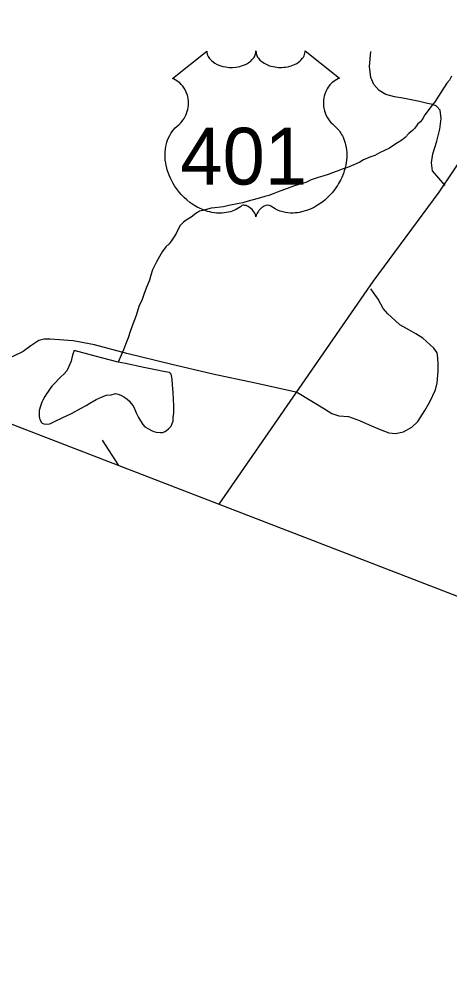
# Model space of a CAD drawing. Extents: x 2001466 to 2224147, y 644118 to 847247.
# Drawn here: x 2055061 to 2056671, y 653811 to 657420 of the extents above; entities that cross this region are included whole.
import ezdxf

# ---------------------------------------------------------------- set-up
doc = ezdxf.new("R2010")
doc.units = 0
for name, color, linetype in [('Exist Boundary Political CountyLine', 7, 'Continuous'), ('Exist Hydrographic Misc Water Feature', 7, 'Continuous'), ('Exist Road Non-System Type 51', 7, 'Continuous'), ('Exist Road Primary US Attributed', 7, 'Continuous'), ('Exist Road Primary US Shield CELL', 7, 'Continuous'), ('Exist Road Primary US Shield Number Label', 7, 'Continuous')]:
    doc.layers.add(name, color=color, linetype=linetype)

msp = doc.modelspace()

# ---------------------------------------------------------------- linework, layer by layer
at = {"layer": 'Exist Boundary Political CountyLine'}
msp.add_lwpolyline([(2025347, 667357.1), (2026293.9, 666990.5), (2073692.9, 648709.4), (2076162.7, 647794.5), (2078580.1, 646988.2), (2083338.8, 645254.9), (2086621.1, 644117.9)], dxfattribs=at)
at = {"layer": 'Exist Hydrographic Misc Water Feature'}
for points in [[(2056677.9, 657206.8), (2056669.9, 657192.8), (2056660.1, 657180.8), (2056652.1, 657166.8), (2056642, 657152.7), (2056632.2, 657136.7), (2056624.2, 657124.7), (2056616.2, 657112.7), (2056600.2, 657092.7), (2056590.2, 657078.7), (2056578.3, 657062.6), (2056570.3, 657048.6), (2056562.3, 657036.6), (2056552.2, 657028.6), (2056540.3, 657012.6), (2056532.3, 657004.6), (2056518.4, 656992.6), (2056504.5, 656978.5), (2056492.4, 656968.5), (2056476.4, 656958.5), (2056458.5, 656946.4), (2056446.4, 656938.4), (2056424.5, 656928.3), (2056408.5, 656920.3), (2056390.4, 656910.3), (2056372.4, 656904.3), (2056348.6, 656894.2), (2056334.7, 656886.2), (2056312.5, 656876.1), (2056288.5, 656866.1), (2056268.6, 656860.1), (2056250.6, 656852.1), (2056232.6, 656846.1), (2056216.8, 656840), (2056196.7, 656834), (2056178.8, 656827.9), (2056152.8, 656819.9), (2056132.7, 656809.9), (2056106.7, 656801.8), (2056086.8, 656795.8), (2056060.9, 656785.7), (2056034.9, 656777.7), (2056010.9, 656767.6), (2055994.9, 656761.6), (2055978.9, 656757.5), (2055954.9, 656749.5), (2055930.9, 656743.5), (2055917, 656739.5), (2055897.1, 656733.4), (2055882.9, 656731.4), (2055863.1, 656727.3), (2055845, 656723.3), (2055824.9, 656719.3), (2055813, 656717.3), (2055792.9, 656715.2), (2055779, 656713.2), (2055747, 656705.1), (2055734.9, 656703.1), (2055726.9, 656697.1), (2055717.1, 656691.1), (2055707.2, 656683.1), (2055697.2, 656677), (2055685.1, 656669), (2055675, 656661), (2055663.1, 656648.9), (2055655.3, 656635), (2055647.3, 656619), (2055639.1, 656605), (2055629.3, 656591), (2055621.3, 656580.9), (2055609.4, 656568.9), (2055595.5, 656550.9), (2055585.4, 656532.8), (2055573.3, 656510.8), (2055559.6, 656482.9), (2055553.4, 656462.8), (2055547.7, 656444.8), (2055537.6, 656420.8), (2055527.6, 656394.8), (2055519.8, 656372.8), (2055507.7, 656346.8), (2055497.9, 656312.8), (2055485.8, 656280.7), (2055475.9, 656252.7), (2055467.9, 656228.7), (2055458.1, 656204.7), (2055450.1, 656184.7), (2055442.1, 656164.7), (2055430.2, 656138.6)], [(2055430.2, 656138.6), (2055368.1, 656154.5), (2055266.1, 656182.3), (2055260.2, 656164.3), (2055256.1, 656148.3), (2055254.1, 656142.3), (2055246.3, 656122.3), (2055238.3, 656106.3), (2055228.2, 656094.3), (2055214.3, 656082.3), (2055190.3, 656056.2), (2055182.3, 656048.2), (2055176.3, 656040.2), (2055168.3, 656028.2), (2055162.4, 656020.2), (2055156.4, 656010.2), (2055148.4, 655996.1), (2055144.6, 655988.1), (2055140.5, 655974.1), (2055134.5, 655958.1), (2055134.5, 655946.1), (2055134.5, 655936.1), (2055136.6, 655928.1), (2055138.6, 655922.1), (2055142.5, 655914.1), (2055146.6, 655910.1), (2055152.5, 655908.2), (2055162.6, 655906.2), (2055174.7, 655908.2), (2055184.5, 655912.2), (2055194.6, 655918.2), (2055220.6, 655930.2), (2055256.5, 655946.4), (2055292.4, 655966.4), (2055310.4, 655976.4), (2055324.4, 655984.5), (2055348.4, 655998.5), (2055370.3, 656008.6), (2055386.3, 656014.6), (2055404.4, 656016.6), (2055420.3, 656020.7), (2055430.4, 656018.6), (2055440.4, 656014.7), (2055452.3, 656008.7), (2055462.4, 656000.7), (2055472.4, 655992.8), (2055478.4, 655984.8), (2055486.4, 655974.8), (2055492.5, 655960.8), (2055498.5, 655948.9), (2055506.5, 655930.9), (2055514.5, 655918.8), (2055522.7, 655904.9), (2055530.7, 655896.9), (2055544.6, 655888.9), (2055554.7, 655883), (2055564.5, 655879), (2055572.5, 655877), (2055588.7, 655875), (2055596.7, 655875), (2055606.5, 655879), (2055618.6, 655889), (2055628.5, 655899.1), (2055632.4, 655909.1), (2055636.5, 655917.1), (2055636.5, 655931.1), (2055638.5, 655947.1), (2055638.3, 655967.1), (2055638.3, 655975.1), (2055636.3, 656025.1), (2055634.2, 656053), (2055632.2, 656075), (2055628.3, 656093), (2055622.3, 656099), (2055600.2, 656102.9), (2055576.2, 656108.9), (2055526.2, 656118.8), (2055458.1, 656132.7), (2055430.2, 656138.6)]]:
    msp.add_lwpolyline(points, dxfattribs=at)
at = {"layer": 'Exist Road Non-System Type 51'}
msp.add_line((2055433.5, 655751.8), (2055372.2, 655846.2), dxfattribs=at)
for points in [[(2056653.6, 656798.2), (2056606.7, 656853.1), (2056603.3, 656883.2), (2056608, 656917.1), (2056623, 656964.8), (2056633.8, 657008.6), (2056638.7, 657048.5), (2056635.3, 657080.5), (2056621.6, 657094.8), (2056607.7, 657101.1), (2056587.8, 657105.5), (2056558, 657112.1), (2056496.2, 657125.4), (2056464.3, 657130), (2056432.5, 657138.7), (2056406.8, 657153.2), (2056387.2, 657175.6), (2056375.8, 657201.8), (2056370.6, 657243.9), (2056375.8, 657299.8)], [(2056101.8, 656025.4), (2056202.6, 655963.3), (2056230.2, 655946.8), (2056256.1, 655938.2), (2056292, 655935.5), (2056333.7, 655920.7), (2056369.4, 655903.9), (2056411, 655887.1), (2056442.8, 655874.4), (2056468.7, 655871.9), (2056498.8, 655877.3), (2056529.2, 655894.7), (2056551.6, 655916.2), (2056578.5, 655957.7), (2056597.1, 655989.3), (2056618, 656034.9), (2056624.6, 656060.8), (2056627.4, 656104.7), (2056628, 656130.7), (2056626.5, 656154.7), (2056624.8, 656172.8), (2056611.2, 656191), (2056570, 656227.9), (2056544.3, 656244.4), (2056518.6, 656258.9), (2056485, 656277.6), (2056467.3, 656293.9), (2056439.8, 656318.5), (2056422.2, 656338.9), (2056402.9, 656373.3), (2056375.7, 656411.8)], [(2056101.8, 656025.4), (2055938.6, 656060.7), (2055785.2, 656093.8), (2055626, 656131), (2055462.8, 656170.3), (2055341.4, 656202.8), (2055261.8, 656218.4), (2055175.9, 656224.2), (2055153.9, 656224.6), (2055133.8, 656219), (2055103.4, 656199.6), (2055074.9, 656178.2), (2055036.6, 656159), (2055000.3, 656147.7), (2054950.3, 656148.8), (2054916.5, 656155.4), (2054880.9, 656176.2), (2054831.8, 656221.2), (2054814, 656229.5), (2054734.3, 656247.1), (2054680.6, 656260.2), (2054619.1, 656283.5), (2054555.2, 656290.8)]]:
    msp.add_lwpolyline(points, dxfattribs=at)
at = {"layer": 'Exist Road Primary US Attributed'}
msp.add_lwpolyline([(2055808.3, 655607.2), (2056384.5, 656440.3), (2056631.5, 656773.3), (2056739.3, 656932.5), (2056804.2, 657056.1), (2056839.7, 657137.8), (2057035.4, 657847.8), (2057102.4, 658134.8), (2057229.1, 658557.8), (2057280.9, 658755.8), (2057376.1, 659063.7), (2057472.4, 659331.8), (2057516.3, 659409.3), (2057768.5, 659813.5), (2058800.4, 661326.8)], dxfattribs=at)
at = {"layer": 'Exist Road Primary US Shield CELL'}
msp.add_lwpolyline([(2055762, 657301.2), (2055762.4, 657295.9), (2055763.6, 657289.6), (2055764.6, 657286.3), (2055767.6, 657280.1), (2055772.5, 657272.7), (2055779.3, 657265.5), (2055786.9, 657259.2), (2055792.1, 657255.8), (2055800.9, 657251.1), (2055810.8, 657246.9), (2055821.9, 657243.7), (2055833.2, 657241.5), (2055845.6, 657240.1), (2055857.8, 657239.9), (2055871, 657240.9), (2055885.6, 657243.7), (2055892.4, 657245.4), (2055899.9, 657248), (2055906.9, 657250.9), (2055914.6, 657255), (2055920.7, 657258.9), (2055925.5, 657262.4), (2055932.4, 657269), (2055937.8, 657275.7), (2055940.1, 657279.5), (2055942, 657283.2), (2055944.7, 657290.9), (2055945.5, 657294.4), (2055946, 657301.5), (2055946.5, 657295.5), (2055947.1, 657291.8), (2055948.1, 657288.1), (2055949.6, 657284.2), (2055952.3, 657278.8), (2055955.4, 657274.2), (2055961.1, 657267.5), (2055964.7, 657264.1), (2055967.9, 657261.5), (2055976.7, 657255.4), (2055986.9, 657250.3), (2055991.9, 657248.1), (2055997.1, 657246.3), (2056003.6, 657244.3), (2056010.4, 657242.7), (2056017, 657241.5), (2056023.9, 657240.6), (2056030.9, 657240), (2056036.6, 657239.9), (2056043.6, 657239.9), (2056050, 657240.3), (2056056.6, 657241.1), (2056063.9, 657242.3), (2056069.8, 657243.6), (2056077.5, 657245.6), (2056084.5, 657248.2), (2056090.6, 657250.8), (2056098.6, 657255), (2056105.1, 657259), (2056109.8, 657262.8), (2056115.4, 657268), (2056120.7, 657274.1), (2056123.8, 657278.6), (2056126, 657283.3), (2056128.1, 657288.1), (2056129.3, 657293.3), (2056129.9, 657297.8), (2056130.1, 657301.6), (2056258.7, 657199.2), (2056255.6, 657198), (2056248.6, 657194.6), (2056243.1, 657191.3), (2056234.3, 657185.1), (2056230.5, 657181.7), (2056226.7, 657178.1), (2056223.2, 657174.3), (2056220.1, 657170.7), (2056216.4, 657165.6), (2056213, 657160.4), (2056209.8, 657154.7), (2056207.4, 657149.7), (2056203.4, 657139.4), (2056201.5, 657132.9), (2056200.3, 657127.3), (2056198.8, 657115.9), (2056198.4, 657110.4), (2056198.4, 657105), (2056198.7, 657099.3), (2056199.2, 657093.8), (2056200.2, 657088.1), (2056201.1, 657083.1), (2056202.7, 657077), (2056205, 657069.8), (2056207.8, 657062.9), (2056213.7, 657051.7), (2056221.3, 657040.3), (2056226.7, 657033.9), (2056232, 657028.5), (2056239.9, 657021.8), (2056244.2, 657018), (2056249.1, 657013), (2056257.2, 657003.7), (2056260.5, 656999.3), (2056263.8, 656994.4), (2056266.8, 656989.3), (2056269.8, 656983.8), (2056272.3, 656979), (2056276.8, 656968), (2056280.1, 656957.3), (2056281.6, 656951.7), (2056284, 656939), (2056284.9, 656932.8), (2056285.9, 656920.5), (2056285.9, 656905.6), (2056284.8, 656891.5), (2056282.1, 656875), (2056279.9, 656865.1), (2056276.6, 656853.6), (2056273.3, 656843.7), (2056267.4, 656829), (2056262.2, 656818.4), (2056255.4, 656805.9), (2056250.8, 656798.4), (2056245.4, 656790.3), (2056238.7, 656781.1), (2056230.8, 656771.2), (2056221.3, 656760.8), (2056213.6, 656753.1), (2056203.6, 656744.1), (2056197.5, 656739.1), (2056188.8, 656732.6), (2056177, 656724.7), (2056165.3, 656717.9), (2056155.3, 656712.8), (2056146.5, 656709), (2056135.1, 656704.7), (2056116.2, 656699.5), (2056109.2, 656698), (2056101, 656696.8), (2056093.4, 656696), (2056085.9, 656695.6), (2056075.9, 656695.6), (2056066, 656696.3), (2056056.5, 656697.7), (2056046.7, 656699.8), (2056036.5, 656702.8), (2056027.2, 656706.4), (2056017.8, 656711.1), (2056001.9, 656721.1), (2055997.3, 656723.5), (2055994.7, 656724.2), (2055988.5, 656724.5), (2055982.8, 656723.3), (2055976.8, 656721), (2055973.3, 656719.1), (2055968.5, 656715.9), (2055964.9, 656713.1), (2055960.5, 656708.9), (2055957.4, 656705.4), (2055955.1, 656702.6), (2055950.6, 656695.6), (2055949, 656692.2), (2055947.4, 656687.9), (2055945.9, 656681.5), (2055943.9, 656689.6), (2055941.5, 656694.9), (2055938.8, 656699.5), (2055935.9, 656703.5), (2055931.5, 656708.6), (2055927.4, 656712.5), (2055922.6, 656716.5), (2055917.4, 656719.6), (2055913.3, 656721.7), (2055909.5, 656723.2), (2055904.8, 656724.3), (2055901, 656724.6), (2055897.9, 656724.5), (2055893.6, 656723.6), (2055887.8, 656719.4), (2055882.3, 656715.6), (2055876.3, 656711.8), (2055869.2, 656708), (2055863.9, 656705.6), (2055857.7, 656703.2), (2055850.4, 656700.7), (2055842.5, 656698.7), (2055834.4, 656697.1), (2055827.3, 656696), (2055819.6, 656695.3), (2055812.7, 656695), (2055805.5, 656695.1), (2055798.7, 656695.7), (2055790.9, 656696.3), (2055781.2, 656697.8), (2055773.1, 656699.6), (2055764.6, 656701.9), (2055755.9, 656704.6), (2055746.5, 656708.2), (2055734.8, 656713.3), (2055726.7, 656717.5), (2055713.9, 656724.8), (2055698.8, 656735.2), (2055687.5, 656744.4), (2055679.2, 656752), (2055666.9, 656764.4), (2055659.8, 656772.6), (2055648.5, 656787.1), (2055641.3, 656797.7), (2055636.6, 656805.5), (2055629.8, 656817.9), (2055626, 656825.7), (2055621.1, 656837.1), (2055617.3, 656847.5), (2055614.1, 656857.4), (2055612.4, 656863.7), (2055610, 656874.8), (2055608.5, 656882.6), (2055607, 656893.3), (2055606.2, 656904.6), (2055606.1, 656915), (2055606.4, 656923.7), (2055607.4, 656933.8), (2055609.1, 656944.5), (2055611.1, 656953.7), (2055613, 656960.3), (2055615.7, 656968.4), (2055619.3, 656977.3), (2055623.6, 656985.8), (2055627.6, 656992.8), (2055632.7, 657000.4), (2055637.7, 657006.9), (2055644.3, 657014), (2055651.1, 657020.6), (2055657.4, 657025.7), (2055664.8, 657033), (2055668.7, 657037.4), (2055673.4, 657043.5), (2055677.1, 657049.2), (2055680.1, 657054.3), (2055684, 657061.8), (2055686.3, 657067.5), (2055689.3, 657076.1), (2055690.8, 657082.2), (2055692.3, 657090), (2055693.3, 657097.4), (2055693.7, 657106.6), (2055693.4, 657114.2), (2055692.5, 657123.1), (2055690.8, 657131.6), (2055688.8, 657139), (2055685.6, 657147.5), (2055682.7, 657153.8), (2055677.7, 657162.2), (2055672.3, 657170), (2055666.6, 657176.4), (2055660.9, 657182.1), (2055655.4, 657186.4), (2055650.2, 657190.1), (2055643.7, 657194), (2055637.4, 657197.2), (2055633.4, 657198.8)], close=True, dxfattribs=at)

# ---------------------------------------------------------------- texts
at = {"layer": 'Exist Road Primary US Shield Number Label'}
msp.add_text('401', height=212.5, dxfattribs=at).set_placement((2055663.2, 656801.9))

doc.saveas('drawing.dxf')
